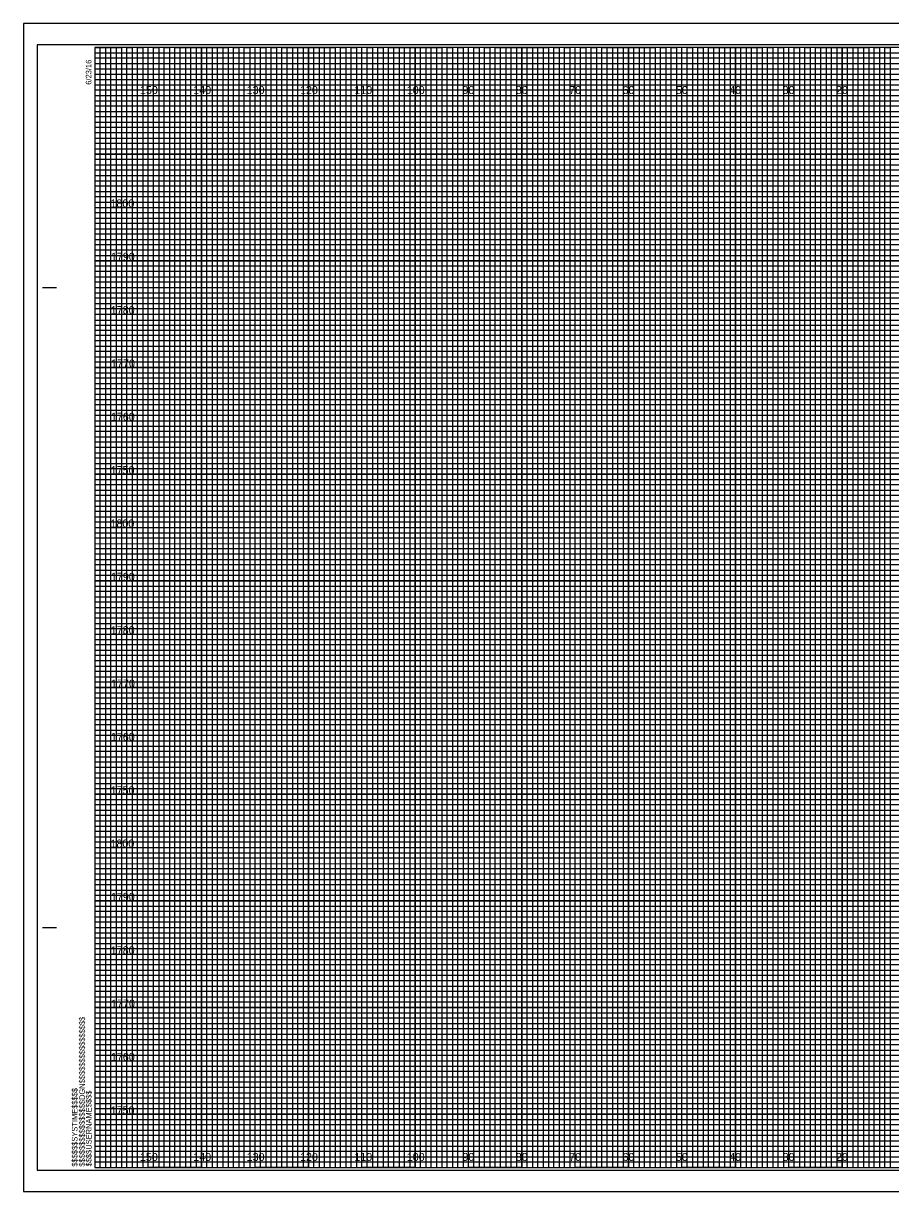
# Model space of a CAD drawing. Extents: x -13 to 323, y -5 to 874.
# Drawn here: x -13.4 to 149.1, y -4.5 to 214.5 of the extents above; entities that cross this region are included whole.
import ezdxf

# ---------------------------------------------------------------- set-up
doc = ezdxf.new("R2010")
doc.units = 0
for name, color, linetype in [('Prop XS DDE', 7, 'Continuous'), ('Prop XS DDE Elevations', 7, 'Continuous'), ('Prop XS DDE Slope Text', 7, 'Continuous'), ('Prop XS Gore Control Minimum', 7, 'Continuous'), ('Prop XS Shoulder Borrow Shape', 7, 'Continuous'), ('Raster_Level_0', 7, 'Continuous'), ('Scratch_Level_3', 7, 'Continuous'), ('Sheet Cutting Line CELL', 7, 'Continuous'), ('Sheet DOT Grid CELL', 7, 'Continuous'), ('Sheet Plot Border Inside CELL', 7, 'Continuous'), ('Sheet Plot Border Outside CELL', 7, 'Continuous')]:
    doc.layers.add(name, color=color, linetype=linetype)

msp = doc.modelspace()

# ---------------------------------------------------------------- linework, layer by layer
at = {"layer": 'Prop XS DDE'}
for p, q in [((0, 209), (260, 209)), ((260, 207.98), (0, 207.98)), ((0, 207.98), (0, 207)), ((0, 207), (260, 207)), ((260, 205.89), (0, 205.89)), ((0, 205.89), (0, 204)), ((0, 204), (320, 204))]:
    msp.add_line(p, q, dxfattribs=at)
for points in [[(0, 203), (270, 203), (320, 203), (320, 202), (0, 202)], [(0, 201), (320, 201), (320, 199), (0, 199)], [(0, 198), (320, 198), (320, 197), (0, 196.98)], [(0, 196), (320, 196), (320, 194), (0, 194)], [(0, 193), (320, 193), (320, 192), (0, 192)], [(0, 191), (320, 191), (320, 189), (0, 189)], [(0, 188), (320, 188), (320, 187), (0, 187)], [(0, 186), (320, 186), (320, 184), (0, 184)], [(0, 183), (320, 183), (320, 182), (0, 182)], [(0, 181), (320, 181), (320, 179), (0, 179)], [(0, 178), (320, 178), (320, 177), (0, 177)], [(0, 176), (320, 176), (320, 173.95), (320, 173), (320, 172), (0, 172)], [(0, 174), (320, 174), (320, 173), (0, 173)], [(0, 171), (320, 171), (320, 169), (0, 169.03)], [(0, 169.03), (320, 169), (320, 168), (0, 168)], [(0, 167), (320, 167), (320, 166), (0, 166)], [(0, 164), (320, 164), (320, 163), (0, 163)], [(0, 162), (320, 162), (320, 161), (0, 161)], [(-0.07, 158.89), (320, 158.89), (320, 157.88), (-0.07, 157.88)], [(0, 157), (320, 157), (320, 156), (0, 156)], [(0, 154), (320, 154), (320, 153), (0, 153)], [(0, 152), (320, 152), (320, 151), (0, 151)], [(0, 149), (320, 149), (320, 148), (0, 148)], [(0, 147), (320, 147), (320, 146), (0, 146)], [(0, 144), (320, 144), (320, 143), (0, 143)], [(0, 142), (320, 142), (320, 141), (0, 141)], [(0, 139), (320, 139), (319.99, 137.98), (0, 138)], [(0, 137), (320, 137), (320, 136), (0, 136)], [(0, 134), (320, 134), (320, 133), (0, 133)], [(0, 132), (320, 132), (320, 131), (0, 131)], [(0, 129), (320, 129), (320, 128), (0, 128)], [(0, 127), (320, 127), (320, 126), (0, 126)], [(0, 124), (320, 124), (320, 123), (0, 123)], [(0, 122), (320, 122), (320, 121), (0, 121)], [(0, 119), (320, 119), (320, 118), (0, 118)], [(0, 116.99), (320.07, 116.91), (320, 116), (0, 116)], [(0, 114), (320, 114), (320, 113), (0, 113)], [(0, 112), (320, 112), (320, 111), (0, 111)], [(0, 109), (320, 109), (320, 108), (0, 108)], [(0, 107), (320, 107), (320, 106), (0, 106)], [(0, 104), (320, 104), (320, 103), (0, 103)], [(0, 102), (320, 102), (320, 101), (0, 101)], [(0, 99), (320, 99), (320, 98), (0, 98)], [(0, 97), (320, 97), (320, 96), (0, 96)], [(0, 94), (320, 94), (320, 93), (0, 93)], [(0, 92), (320, 92), (320, 91), (0, 91)], [(0, 89), (320, 89), (320, 88), (0, 88)], [(0, 87), (320, 87), (320, 86), (0, 86)], [(0, 84), (320, 84), (320, 83), (0, 83)], [(0, 82), (320, 82), (320, 81), (0, 81)], [(0, 79), (320, 79), (319.99, 77.98), (0, 78)], [(0, 77), (320, 77), (320, 76), (0, 76)], [(0, 74), (320, 74), (320, 73), (0, 73)], [(0, 72), (320, 72), (320, 71), (0, 71)], [(0, 69), (320, 69), (320, 68), (0, 68)], [(0, 67), (320, 67), (320, 66), (0, 66)], [(0, 64), (320, 64), (320, 63), (0, 63)], [(0, 62), (320, 62), (320, 61), (0, 61)], [(0, 59), (320, 59), (320, 58), (0, 58)], [(0, 56.99), (320.07, 56.91), (320, 56), (0, 56)], [(0, 54), (320, 54), (320, 53), (0, 53)], [(0, 52), (320, 52), (320, 51), (0, 51)], [(0, 49), (320, 49), (320, 48), (0, 48)], [(0, 47), (320, 47), (320, 46), (0, 46)], [(0, 44), (320, 44), (320, 43), (0, 43)], [(0, 42), (320, 42), (320, 41), (0, 41)], [(0, 39), (320, 39), (320, 38), (0, 38)], [(0, 37), (320, 37), (320, 36), (0, 36)], [(0, 34), (320, 34), (320, 33), (0, 33)], [(0, 32), (320, 32), (320, 31), (0, 31)], [(0, 29), (320, 29), (320, 28), (0, 28)], [(0, 27), (320, 27), (320, 26), (0, 26)], [(0, 24), (320, 24), (320, 23), (0, 23)], [(0, 22), (320, 22), (320, 21), (0, 21)], [(0, 19), (320, 19), (320, 18), (0, 18)], [(0, 17), (320, 17), (320, 16), (0, 16)], [(0, 14), (320, 14), (320, 13), (0, 13)], [(0, 12), (320, 12), (320, 11), (0, 11)], [(0, 9), (320, 9), (320, 8), (0, 8)], [(0, 7), (320, 7), (320, 6), (0, 6)], [(0, 4), (320, 4), (320, 3), (0, 3)], [(0, 2), (320, 2), (320, 1), (0, 1)]]:
    msp.add_lwpolyline(points, dxfattribs=at)
at = {"layer": 'Prop XS DDE Elevations'}
for points in [[(0, 0), (1, 0), (1, 210), (2, 210), (2, 0)], [(2, 0), (3, 0), (3, 210), (4, 210), (4, 0)], [(5, 0), (6, 0), (6, 210), (7, 210), (7, 0)], [(7, 0), (8, 0), (8, 210), (9, 210), (9, 0)], [(10, 0), (11, 0), (11, 210), (12, 210), (12, 0)], [(12, 0), (13, 0), (13, 210), (14, 210), (14, 0)], [(15, 0), (16, 0), (16, 210), (17, 210), (17, 0)], [(17, 0), (18, 0), (18, 210), (19, 210), (19, 0)], [(20, 0), (21, 0), (21, 210), (22, 210), (22, 0)], [(22, 0), (23, 0), (23, 210), (24, 210), (24, 0)], [(25, 0), (26, 0), (26, 210), (27, 210), (27, 0)], [(27, 0), (28, 0), (28, 210), (29, 210), (29, 0)], [(30, 0), (31, 0), (31, 210), (32, 210), (32, 0)], [(32, 0), (33, 0), (33, 210), (34, 210), (34, 0)], [(35, 0), (36, 0), (36, 210), (37, 210), (37, 0)], [(37, 0), (38, 0), (38, 210), (39, 210), (39, 0)], [(40, 0), (41, 0), (41, 210), (42, 210), (42, 0)], [(42, 0), (43, 0), (43, 210), (44, 210), (44, 0)], [(45, 0), (46, 0), (46, 210), (47, 210), (47, 0)], [(47, 0), (48, 0), (48, 210), (49, 210), (49, 0)], [(50, 0), (51, 0), (51, 210), (52, 210), (52, 0)], [(52, 0), (53, 0), (53, 210), (54, 210), (54, 0)], [(55, 0), (56, 0), (56, 210), (57, 210), (57, 0)], [(57, 0), (58, 0), (58, 210), (59, 210), (59, 0)], [(60, 0), (61, 0), (61, 210), (62, 210), (62, 0)], [(62, 0), (63, 0), (63, 210), (64, 210), (64, 0)], [(65, 0), (66, 0), (66, 210), (67, 210), (67, 0)], [(67, 0), (68, 0), (68, 210), (69, 210), (69, 0)], [(70, 0), (71, 0), (71, 210), (72, 210), (72, 0)], [(72, 0), (73, 0), (73, 210), (74, 210), (74, 0)], [(75, 0), (76, 0), (76, 210), (77, 210), (77, 0)], [(77, 0), (78, 0), (78, 210), (79, 210), (79, 0)], [(80, 0), (81, 0), (81, 210), (82, 210), (82, 0)], [(82, 0), (83, 0), (83, 210), (84, 210), (84, 0)], [(85, 0), (86, 0), (86, 210), (87, 210), (87, 0)], [(87, 0), (88, 0), (88, 210), (89, 210), (89, 0)], [(90, 0), (91, 0), (91, 210), (92, 210), (92, 0)], [(92, 0), (93, 0), (93, 210), (94, 210), (94, 0)], [(95, 0), (96, 0), (96, 210), (97, 210), (97, 0)], [(97, 0), (98, 0), (98, 210), (99, 210), (99, 0)], [(100, 0), (101, 0), (101, 210), (102, 210), (102, 0)], [(102, 0), (103, 0), (103, 210), (104, 210), (104, 0)], [(105, 0), (106, 0), (106, 210), (107, 210), (107, 0)], [(107, 0), (108, 0), (108, 210), (109, 210), (109, 0)], [(110, 0), (111, 0), (111, 210), (112, 210), (112, 0)], [(112, 0), (113, 0), (113, 210), (114, 210), (114, 0)], [(115, 0), (116, 0), (116, 210), (117, 210), (117, 0)], [(117, 0), (118, 0), (118, 210), (119, 210), (119, 0)], [(120, 0), (121, 0), (121, 210), (122, 210), (122, 0)], [(122, 0), (123, 0), (123, 210), (124, 210), (124, 0)], [(125, 0), (126, 0), (126, 210), (127, 210), (127, 0)], [(127, 0), (128, 0), (128, 210), (129, 210), (129, 0)], [(130, 0), (131, 0), (131, 210), (132, 210), (132, 0)], [(132, 0), (133, 0), (133, 210), (134, 210), (134, 0)], [(135, 0), (136, 0), (136, 210), (137, 210), (137, 0)], [(137, 0), (138, 0), (138, 210), (139, 210), (139, 0)], [(140, 0), (141, 0), (141, 210), (142, 210), (142, 0)], [(142, 0), (143, 0), (143, 210), (144, 210), (144, 0)], [(145, 0), (146, 0), (146, 210), (147, 210), (147, 0)], [(147, 0), (148, 0), (148, 210), (149, 210), (149, 0)]]:
    msp.add_lwpolyline(points, dxfattribs=at)
at = {"layer": 'Prop XS DDE Slope Text'}
for p, q in [((-9.8, 165), (-7.3, 165)), ((-9.7, 165), (-7.2, 165)), ((-9.8, 45), (-7.3, 45)), ((-9.7, 45), (-7.2, 45)), ((0, 0), (0, 0)), ((0, 0), (0, 0)), ((0, 0), (0, 0)), ((0, 0), (0, 0)), ((0, 0), (0, 0)), ((0, 0), (0, 0)), ((0, 0), (0, 0))]:
    msp.add_line(p, q, dxfattribs=at)
msp.add_lwpolyline([(320, 210), (0, 210), (0, 0), (320, 0)], close=True, dxfattribs=at)
at = {"layer": 'Prop XS Gore Control Minimum'}
for p, q in [((10, 210), (0, 210)), ((10, 0), (10, 210)), ((30, 210), (20, 210)), ((20, 210), (20, 0)), ((30, 0), (30, 210)), ((50, 210), (40, 210)), ((40, 210), (40, 0)), ((50, 0), (50, 210)), ((70, 210), (60, 210)), ((60, 210), (60, 0)), ((70, 0), (70, 210)), ((90, 210), (80, 210)), ((80, 210), (80, 0)), ((90, 0), (90, 210)), ((110, 210), (100, 210)), ((100, 210), (100, 0)), ((110, 0), (110, 210)), ((130, 210), (120, 210)), ((120, 210), (120, 0)), ((130, 0), (130, 210)), ((150, 210), (140, 210)), ((140, 210), (140, 0)), ((20, 0), (10, 0)), ((40, 0), (30, 0)), ((60, 0), (50, 0)), ((80, 0), (70, 0)), ((100, 0), (90, 0)), ((120, 0), (110, 0)), ((140, 0), (130, 0))]:
    msp.add_line(p, q, dxfattribs=at)
for points in [[(0, 200), (320, 200), (320, 190), (0, 190)], [(0, 180), (320, 180), (320, 170), (0, 170)], [(0, 160), (320, 160), (320, 150), (0, 150)], [(0, 140), (320, 140), (320, 130), (0, 130)], [(0, 120), (320, 120), (320, 110), (0, 110)], [(0, 100), (320, 100), (320, 90), (0, 90)], [(0, 80), (320, 80), (320, 70), (0, 70)], [(0, 60), (320, 60), (320, 50), (0, 50)], [(0, 40), (320, 40), (320, 30), (0, 30)], [(0, 20), (320, 20), (320, 10), (0, 10)]]:
    msp.add_lwpolyline(points, dxfattribs=at)
at = {"layer": 'Prop XS Shoulder Borrow Shape'}
for points in [[(0, 210), (5, 210), (5, 0), (15, 0), (15, 210), (25, 210), (25, 0), (35, 0), (35, 210), (45, 210), (45, 0), (55, 0), (55, 210), (65, 210), (65, 0), (75, 0), (75, 210), (85, 210), (85, 0), (95, 0), (95, 210), (105, 210), (105, 0), (115, 0), (115, 210), (125, 210), (125, 0), (135, 0), (135, 210), (145, 210), (145, 0), (155, 0)], [(0, 205), (275, 205)], [(0, 185), (320, 185), (320, 195), (0, 195)], [(0, 165), (320, 165), (320, 175), (0, 175)], [(0, 145), (320, 145), (320, 155), (0, 155)], [(0, 125), (320, 125), (320, 135), (0, 135)], [(0, 105), (320, 105), (320, 115), (0, 115)], [(0, 85), (320, 85), (320, 95), (0, 95)], [(0, 65), (320, 65), (320, 75), (0, 75)], [(0, 45), (320, 45), (320, 55), (0, 55)], [(0, 25), (320, 25), (320, 35), (0, 35)], [(0, 5), (320, 5), (320, 15), (0, 15)]]:
    msp.add_lwpolyline(points, dxfattribs=at)
at = {"layer": 'Sheet Cutting Line CELL'}
for p, q in [((323.3, 214.5), (-13.4, 214.5)), ((-13.4, 214.5), (-13.4, -4.5)), ((-13.4, -4.5), (323.3, -4.5))]:
    msp.add_line(p, q, dxfattribs=at)
at = {"layer": 'Sheet DOT Grid CELL'}
for p, q in [((10, 0), (10, 210)), ((20, 0), (20, 210)), ((30, 0), (30, 210)), ((40, 0), (40, 210)), ((50, 0), (50, 210)), ((60, 0), (60, 210)), ((70, 0), (70, 210)), ((80, 0), (80, 210)), ((90, 0), (90, 210)), ((100, 0), (100, 210)), ((110, 0), (110, 210)), ((120, 0), (120, 210)), ((130, 0), (130, 210)), ((140, 0), (140, 210)), ((0, 200), (320, 200)), ((0, 190), (320, 190)), ((0, 180), (320, 180)), ((0, 170), (320, 170)), ((0, 160), (320, 160)), ((0, 150), (320, 150)), ((0, 140), (320, 140)), ((0, 130), (320, 130)), ((0, 120), (320, 120)), ((0, 110), (320, 110)), ((0, 100), (320, 100)), ((0, 90), (320, 90)), ((0, 80), (320, 80)), ((0, 70), (320, 70)), ((0, 60), (320, 60)), ((0, 50), (320, 50)), ((0, 40), (320, 40)), ((0, 30), (320, 30)), ((0, 20), (320, 20)), ((0, 10), (320, 10))]:
    msp.add_line(p, q, dxfattribs=at)
at = {"layer": 'Sheet Plot Border Inside CELL'}
msp.add_lwpolyline([(-10.8, -0.5), (322.4, -0.5), (322.4, 210.5), (-10.8, 210.5)], close=True, dxfattribs=at)
at = {"layer": 'Sheet Plot Border Outside CELL'}
msp.add_lwpolyline([(-13.4, -4.5), (323.3, -4.5), (323.3, 214.5), (-13.4, 214.5)], close=True, dxfattribs=at)

# ---------------------------------------------------------------- texts
at = {"layer": 'Prop XS DDE Slope Text'}
for s, p in [('6/23/16', (-0.65, 203)), ('$$$$$$$$$$$$$$$$DGN$$$$$$$$$$$$$$$$', (-1.88, 0.18)), ('$$$$$$SYSTIME$$$$$', (-3.26, 0.18)), ('$$$$USERNAME$$$$', (-0.62, 0.23))]:
    msp.add_text(s, height=1.05, rotation=90, dxfattribs=at).set_placement(p)
at = {"layer": 'Raster_Level_0'}
for s, p in [('150', (8.44, 201.25)), ('140', (18.44, 201.25)), ('130', (28.44, 201.25)), ('120', (38.44, 201.25)), ('110', (48.62, 201.25)), ('100', (58.44, 201.25)), ('90', (68.86, 201.25)), ('80', (78.86, 201.25)), ('70', (88.86, 201.25)), ('60', (98.86, 201.25)), ('50', (108.86, 201.25)), ('40', (118.86, 201.25)), ('30', (128.86, 201.25)), ('20', (138.86, 201.25)), ('150', (8.44, 1.25)), ('140', (18.44, 1.25)), ('130', (28.44, 1.25)), ('120', (38.44, 1.25)), ('110', (48.62, 1.25)), ('100', (58.44, 1.25)), ('90', (68.86, 1.25)), ('80', (78.86, 1.25)), ('70', (88.86, 1.25)), ('60', (98.86, 1.25)), ('50', (108.86, 1.25)), ('40', (118.86, 1.25)), ('30', (128.86, 1.25)), ('20', (138.86, 1.25))]:
    msp.add_text(s, height=1.5, dxfattribs=at).set_placement(p)
at = {"layer": 'Scratch_Level_3'}
for s, p in [('1800', (2.92, 180)), ('1790', (3, 170)), ('1780', (2.98, 160)), ('1770', (3.04, 150)), ('1760', (3, 140)), ('1750', (2.96, 130)), ('1800', (2.92, 120)), ('1790', (3, 110)), ('1780', (2.98, 100)), ('1770', (3.04, 90)), ('1760', (3, 80)), ('1750', (2.96, 70)), ('1800', (2.92, 60)), ('1790', (3, 50)), ('1780', (2.98, 40)), ('1770', (3.04, 30)), ('1760', (3, 20)), ('1750', (2.96, 10))]:
    msp.add_text(s, height=1.5, dxfattribs=at).set_placement(p)

doc.saveas('drawing.dxf')
